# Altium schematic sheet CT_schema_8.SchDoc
size 287 x 160 mm
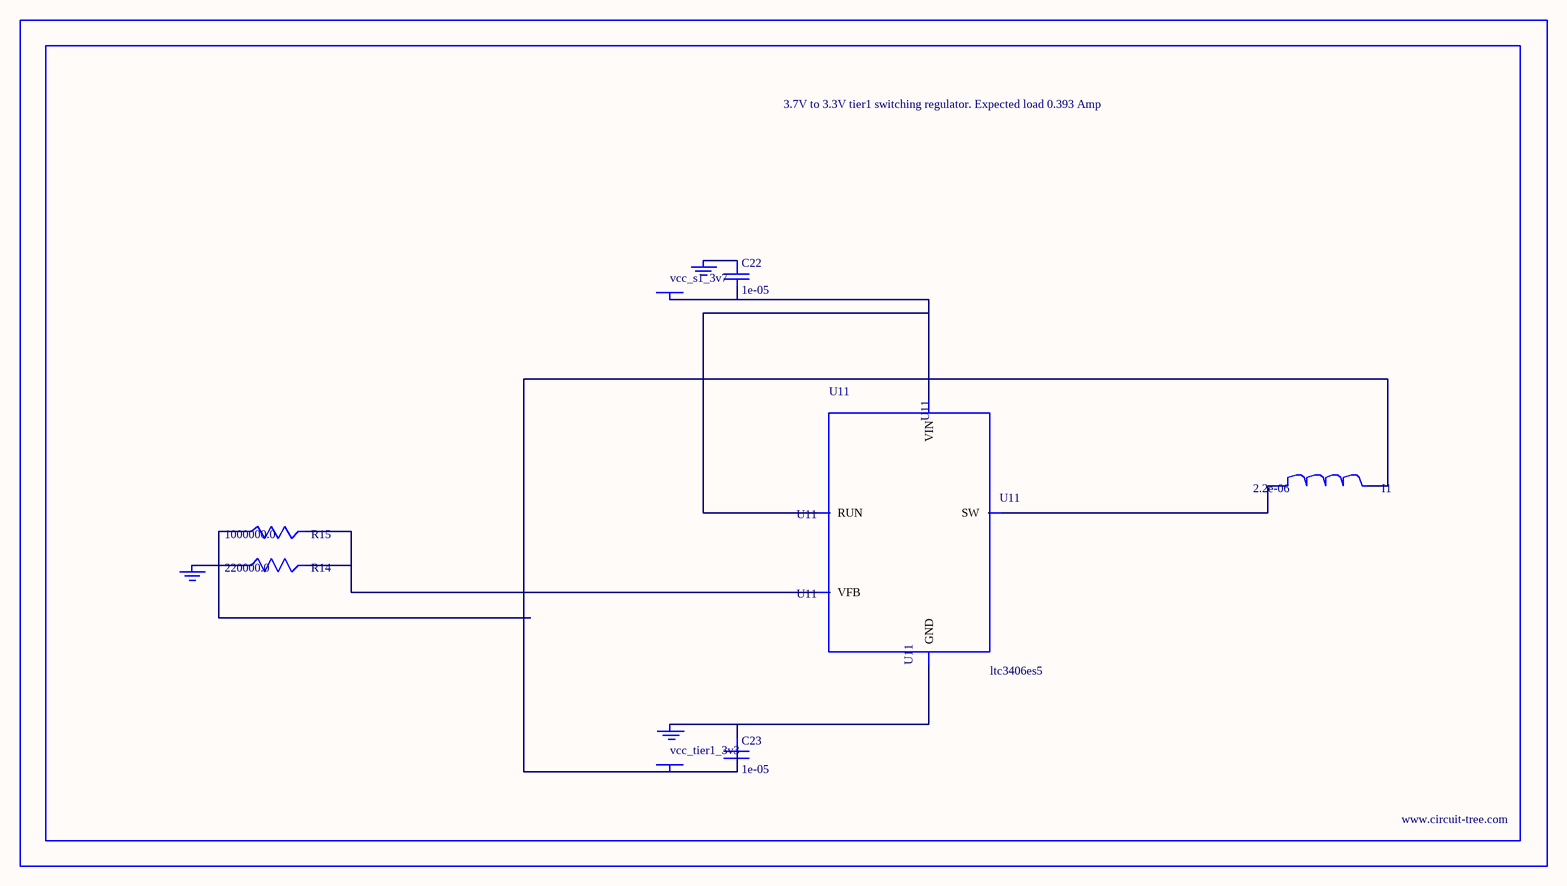
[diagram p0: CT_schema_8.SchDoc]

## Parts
BORDER7  (no value)
C22  1e-05  [C0805]
C23  1e-05  [C0805]
GND_INSTANCE_7_0  (no value)
GND_INSTANCE_7_1  (no value)
GND_INSTANCE_7_2  (no value)
I1  2.2e-06  [L0805]
POWER_INSTANCE_7_0  vcc_tier1_3v3
POWER_INSTANCE_7_1  vcc_s1_3v7
R14  220000.0  [R0603]
R15  1000000.0  [R0603]
U11  ltc3406es5  [TSOT-23-5]

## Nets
NetC22_1: C22.1 GND_INSTANCE_7_1.0(GND)
NetC22_2: C22.2 POWER_INSTANCE_7_1.0(PWR) U11.1(RUN) U11.4(VIN)
NetC23_1: C23.1 GND_INSTANCE_7_0.0(GND) U11.2(GND)
NetC23_2: C23.2 I1.2 POWER_INSTANCE_7_0.0(PWR) R15.1
NetGND_INSTANCE_7_2_0: GND_INSTANCE_7_2.0(GND) R14.1
NetI1_1: I1.1 U11.3(SW)
NetR14_2: R14.2 R15.2 U11.5(VFB)

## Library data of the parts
BORDER7 = BORDER_PAGE7
C22 C23 = C0805C106K8RACTU
GND_INSTANCE_7_0-GND_INSTANCE_7_2 = GND
I1 = L0805C2R2MDWIT
POWER_INSTANCE_7_0 POWER_INSTANCE_7_1 = PWR
R14 = RC0603JR-07220KL
R15 = RC0603JR-071ML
